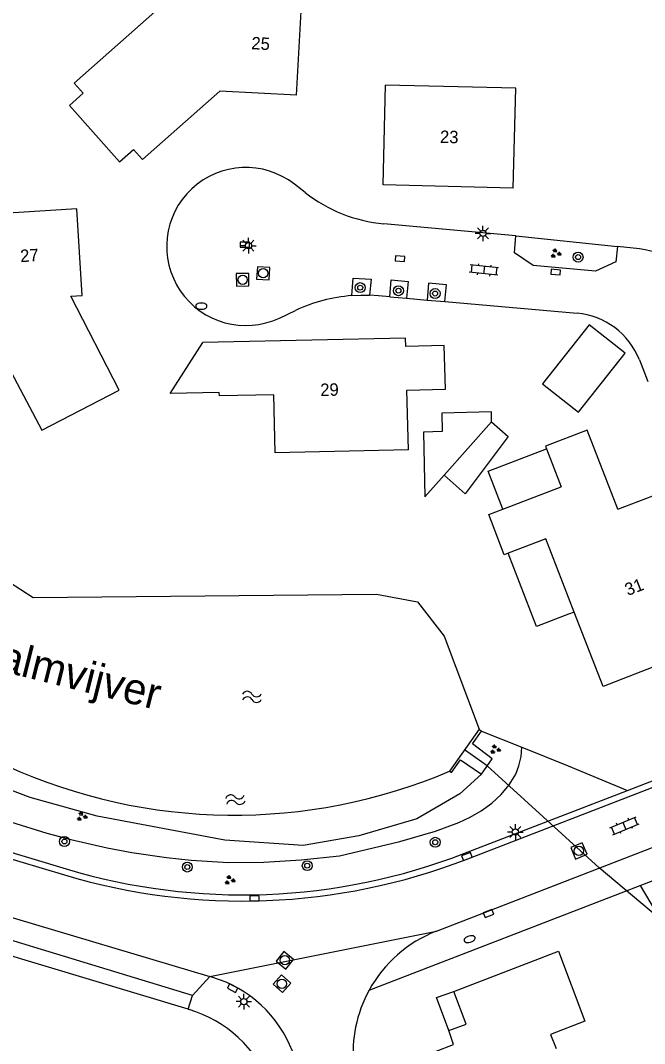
# Model space of a CAD drawing. Extents: x 131000 to 133013, y 393000 to 396501.
# Drawn here: x 131308.3 to 131358.5, y 394977.7 to 395059.9 of the extents above; entities that cross this region are included whole.
import ezdxf

# ---------------------------------------------------------------- set-up
doc = ezdxf.new("R2010")
doc.units = 0
for name, color, linetype in [('gg-afsc-erfafscheiding', 7, 'Continuous'), ('gg-anno-huisnummerreeks BGT', 7, 'Continuous'), ('gg-anno-naam water', 7, 'Continuous'), ('gg-bbg-gedigitaliseerde bebouwing', 7, 'Continuous'), ('gg-bbg-gedigitaliseerde bijgebouw', 7, 'Continuous'), ('gg-bbg-hoofdgebouw', 7, 'Continuous'), ('gg-bbg-luifel en loopbrug', 7, 'Continuous'), ('gg-knt-BGT kruinlijn', 7, 'Continuous'), ('gg-knt-verharding', 7, 'Continuous'), ('gg-knt-verharding nz', 7, 'Continuous'), ('gg-kntw-beschoeiing', 7, 'Continuous'), ('gg-kwrk-duiker nz buis', 7, 'Continuous'), ('gg-kwrk-uitstroombak niveau min 01', 7, 'Continuous'), ('gt-grn-groengrens', 7, 'Continuous'), ('gt-grn-vlakafsluiter', 7, 'Continuous'), ('gt-grn-weggrens', 7, 'Continuous'), ('gt-symb-boom', 7, 'Continuous'), ('gt-symb-brandkraan', 7, 'Continuous'), ('gt-symb-groenvak', 7, 'Continuous'), ('gt-symb-klinker verharding', 7, 'Continuous'), ('gt-symb-kolk', 7, 'Continuous'), ('gt-symb-lichtmast', 7, 'Continuous'), ('gt-symb-rioolschacht', 7, 'Continuous'), ('gt-symb-watersymbool', 7, 'Continuous')]:
    doc.layers.add(name, color=color, linetype=linetype)

# ---------------------------------------------------------------- blocks, each defined once
blk = doc.blocks.new('gt0-LMAST')
at = {"layer": 'gt-symb-lichtmast'}
for p, q in [((-0.182, 0.173), (-0.447, 0.438)), ((-0.005, 0.246), (-0.005, 0.621)), ((0.172, 0.173), (0.437, 0.438)), ((-0.255, -0.004), (-0.63, -0.004)), ((-0.182, -0.181), (-0.447, -0.446)), ((-0.005, -0.254), (-0.005, -0.629)), ((0.437, -0.446), (0.172, -0.181)), ((0.245, -0.004), (0.62, -0.004))]:
    blk.add_line(p, q, dxfattribs=at)
blk.add_circle((-0.005, -0.004), 0.25, dxfattribs=at)
blk = doc.blocks.new('gt0-BR')
at = {"layer": 'gt-symb-brandkraan'}
for centre, radius, start, end in [((-0.244, 0), 0.206, 107.56694, 252.43307), ((0.599, -2.664), 3, 106.89205, 107.56694), ((0, -0.691), 0.938, 73.10799, 106.89205), ((-0.599, -2.664), 3, 72.43309, 73.10799), ((0.244, 0), 0.206, 287.56695, 72.43309), ((0.599, 2.664), 3, 252.43307, 253.10797), ((0, 0.691), 0.938, 253.10797, 286.89206), ((-0.599, 2.664), 3, 286.89206, 287.56695)]:
    blk.add_arc(centre, radius, start, end, dxfattribs=at)
blk = doc.blocks.new('gt0-RS')
at = {"layer": 'gt-symb-rioolschacht'}
blk.add_lwpolyline([(-0.5, -0.5), (0.5, -0.5), (0.5, 0.5), (-0.5, 0.5)], close=True, dxfattribs=at)
blk.add_circle((0, 0), 0.375, dxfattribs=at)
blk = doc.blocks.new('gt0-KOLK')
at = {"layer": 'gt-symb-kolk'}
blk.add_lwpolyline([(0, 0), (0.375, 0), (0.375, 0.4), (-0.375, 0.4), (-0.375, 0), (0, 0)], dxfattribs=at)
blk = doc.blocks.new('gt0-KL1')
at = {"layer": 'gt-symb-klinker verharding'}
for p, q in [((-1.15, 0.3), (1.15, 0.3)), ((-1, -0.3), (-1, 0.3)), ((-0.5, 0.3), (-0.5, 0.45)), ((0, -0.3), (0, 0.3)), ((0.5, 0.3), (0.5, 0.45)), ((1, -0.3), (1, 0.3)), ((-1.15, -0.3), (1.15, -0.3)), ((-0.5, -0.45), (-0.5, -0.3)), ((0.5, -0.45), (0.5, -0.3))]:
    blk.add_line(p, q, dxfattribs=at)
blk = doc.blocks.new('gt0-BOOM')
at = {"layer": 'gt-symb-boom'}
for radius in [0.4, 0.2]:
    blk.add_circle((0, 0), radius, dxfattribs=at)
blk = doc.blocks.new('gt0-GRVAK')
at = {"layer": 'gt-symb-groenvak'}
for p, q in [((-0.11, 0.189), (-0.228, 0.24)), ((-0.182, 0.153), (0.088, 0.153)), ((-0.091, 0.211), (-0.156, 0.322)), ((-0.047, 0.214), (-0.047, 0.393)), ((-0.004, 0.211), (0.061, 0.322)), ((0.015, 0.189), (0.133, 0.24)), ((0.262, -0.052), (0.197, 0.059)), ((0.305, -0.049), (0.305, 0.13)), ((0.349, -0.052), (0.414, 0.059)), ((-0.245, -0.228), (-0.363, -0.177)), ((-0.318, -0.264), (-0.047, -0.264)), ((-0.226, -0.206), (-0.291, -0.095)), ((-0.183, -0.203), (-0.183, -0.024)), ((-0.139, -0.206), (-0.074, -0.095)), ((-0.12, -0.228), (-0.002, -0.177)), ((0.243, -0.074), (0.125, -0.023)), ((0.17, -0.11), (0.441, -0.11)), ((0.368, -0.074), (0.486, -0.023))]:
    blk.add_line(p, q, dxfattribs=at)
blk = doc.blocks.new('gt0-WA')
at = {"layer": 'gt-symb-watersymbool'}
for centre, start, end in [((-0.323, 0.022), 28.07249, 151.92751), ((0.427, 0.422), 208.07248, 331.92751), ((-0.323, -0.428), 28.07249, 151.92751), ((0.427, -0.028), 208.07248, 331.92751)]:
    blk.add_arc(centre, 0.425, start, end, dxfattribs=at)

msp = doc.modelspace()

# ---------------------------------------------------------------- linework, layer by layer
at = {"layer": 'gg-afsc-erfafscheiding'}
msp.add_line((131358.103, 394990.382), (131360.379, 394986.536), dxfattribs=at)
at = {"layer": 'gg-bbg-gedigitaliseerde bebouwing'}
for p, q in [((131324.19, 395034.066), (131322.954, 395034.039)), ((131355.123, 395006.38), (131352.801, 395012.379))]:
    msp.add_line(p, q, dxfattribs=at)
for points in [[(131330.48, 395053.926), (131330.94, 395062.15), (131321.42, 395062.73), (131312.605, 395054.893)], [(131312.605, 395054.893), (131313.326, 395054.086), (131312.22, 395053.099), (131316.259, 395048.575), (131317.365, 395049.562)], [(131347.906, 395046.447), (131348.12, 395054.49), (131337.638, 395054.741)], [(131312.82, 395044.801), (131303.03, 395044.19), (131303.48, 395037.21), (131304.54, 395037.29), (131310, 395027), (131316.237, 395030.206)], [(131324.277, 395030.022), (131320.322, 395029.936), (131322.954, 395034.039)], [(131339.472, 395025.408), (131328.759, 395025.178), (131328.659, 395029.842), (131324.283, 395029.749), (131324.277, 395030.022)], [(131347.495, 395017.107), (131347.18, 395016.986), (131345.943, 395020.208)], [(131352.801, 395012.379), (131350.52, 395018.27), (131347.495, 395017.107)], [(131351.529, 394985.097), (131353.67, 394979.492), (131350.907, 394978.402), (131351.347, 394977.285)]]:
    msp.add_lwpolyline(points, dxfattribs=at)
at = {"layer": 'gg-bbg-gedigitaliseerde bijgebouw'}
for p, q in [((131346.169, 395027.665), (131346.152, 395028.465)), ((131342.346, 395023.383), (131346.169, 395027.665))]:
    msp.add_line(p, q, dxfattribs=at)
msp.add_lwpolyline([(131346.152, 395028.465), (131342.153, 395028.379), (131342.185, 395026.879), (131340.686, 395026.847), (131340.797, 395021.648), (131342.346, 395023.383)], dxfattribs=at)
at = {"layer": 'gg-bbg-hoofdgebouw'}
for p, q in [((131350.581, 395025.503), (131351.761, 395022.444)), ((131347.065, 395020.639), (131351.761, 395022.444)), ((131345.943, 395020.208), (131347.065, 395020.639)), ((131343.12, 394981.878), (131351.529, 394985.097))]:
    msp.add_line(p, q, dxfattribs=at)
for points in [[(131347.906, 395046.447), (131337.439, 395046.713), (131337.638, 395054.741)], [(131330.48, 395053.926), (131324.309, 395054.266), (131318.091, 395048.748), (131317.365, 395049.562)], [(131316.237, 395030.206), (131312.345, 395037.778), (131313.245, 395037.828), (131312.82, 395044.801)], [(131339.472, 395025.408), (131339.358, 395030.219), (131342.445, 395030.286), (131342.358, 395033.809), (131339.263, 395033.733), (131339.249, 395034.389), (131324.19, 395034.066)], [(131356.303, 395020.645), (131353.848, 395027.009), (131350.499, 395025.717), (131350.581, 395025.503)], [(131356.303, 395020.645), (131359.113, 395021.728), (131363.745, 395009.735), (131355.123, 395006.38)], [(131342.72, 394978.732), (131344.127, 394979.25), (131343.12, 394981.878)], [(131342.617, 394969.749), (131340.041, 394976.421), (131343.11, 394977.594), (131342.72, 394978.732)]]:
    msp.add_lwpolyline(points, dxfattribs=at)
at = {"layer": 'gg-bbg-luifel en loopbrug'}
for points in [[(131350.247, 395030.736), (131353.141, 395028.443), (131356.897, 395033.183), (131354.003, 395035.476), (131350.247, 395030.736)], [(131346.169, 395027.665), (131347.484, 395026.491), (131344.04, 395021.87), (131342.346, 395023.383)], [(131347.065, 395020.639), (131345.889, 395023.7), (131350.581, 395025.503)], [(131352.801, 395012.379), (131352.336, 395012.199), (131349.778, 395011.209), (131347.495, 395017.107)], [(131342.72, 394978.732), (131341.748, 394981.373), (131343.12, 394981.878)]]:
    msp.add_lwpolyline(points, dxfattribs=at)
at = {"layer": 'gg-knt-BGT kruinlijn'}
msp.add_lwpolyline([(131307.503, 394995.513), (131310.414, 394994.609), (131312.345, 394994.086), (131315.271, 394993.413), (131317.239, 394993.042), (131320.031, 394992.63), (131322.024, 394992.421), (131325.023, 394992.248), (131327.861, 394992.259), (131330.854, 394992.456), (131333.939, 394992.769), (131338.798, 394993.922), (131341.658, 394994.751), (131343.543, 394995.459), (131344.448, 394995.893), (131345.314, 394996.397), (131346.174, 394997.015), (131346.931, 394997.7), (131347.589, 394998.474), (131348.108, 394999.335), (131348.352, 395000), (131348.543, 395000.768), (131348.594, 395001.499)], dxfattribs=at)
at = {"layer": 'gg-knt-verharding'}
for p, q in [((131331.178, 395046.101), (131330.309, 395046.778)), ((131348.122, 395042.623), (131337.5, 395043.598)), ((131358.048, 395041.566), (131356.278, 395041.755)), ((131337.977, 395037.729), (131339.331, 395037.609)), ((131339.331, 395037.609), (131340.983, 395037.464)), ((131340.983, 395037.464), (131342.408, 395037.338)), ((131329.102, 395036.012), (131330.408, 395036.624)), ((131342.408, 395037.338), (131353.031, 395036.4)), ((131358.047, 395032.659), (131358.735, 395030.922)), ((131341.741, 394986.723), (131394.294, 395007.136)), ((131321.784, 394980.439), (131247.188, 395002.933)), ((131344.118, 394992.489), (131367.358, 395001.475)), ((131357.088, 394998.04), (131362.158, 395000)), ((131290.008, 394998.327), (131311.973, 394991.725)), ((131343.938, 394992.956), (131357.088, 394998.04)), ((131290.124, 394997.77), (131311.829, 394991.246)), ((131358.103, 394990.382), (131375.199, 394996.998)), ((131336.315, 394981.973), (131358.103, 394990.382)), ((131323.51, 394983.065), (131322.115, 394981.536)), ((131323.744, 394982.995), (131323.51, 394983.065)), ((131321.784, 394980.439), (131321.841, 394980.422))]:
    msp.add_line(p, q, dxfattribs=at)
for points in [[(131356.278, 395041.755), (131356.138, 395040.542), (131354.52, 395039.782), (131349.513, 395040.233), (131348.004, 395041.261), (131348.122, 395042.623)], [(131334.917, 395037.818), (131335.042, 395039.23), (131336.474, 395039.137), (131336.36, 395037.851)], [(131337.977, 395037.729), (131338.096, 395039.074), (131339.45, 395038.955), (131339.331, 395037.609)], [(131342.408, 395037.338), (131342.527, 395038.681), (131341.102, 395038.817), (131340.983, 395037.464)], [(131334.917, 395037.818), (131335.64, 395037.855), (131336.36, 395037.851)], [(131337.977, 395037.729), (131337.081, 395037.808), (131336.36, 395037.851)], [(131322.115, 394981.536), (131296.231, 394989.423), (131295.776, 394991.367)]]:
    msp.add_lwpolyline(points, dxfattribs=at)
for centre, radius, start, end in [((131326.401, 395041.765), 6.356, 52.05994, 295.14637), ((131338.601, 395055.614), 12.066, 232.03555, 264.76535), ((131357.334, 395034.859), 6.745, 21.10055, 83.92424), ((131335.94, 395024.842), 13.016, 94.50994, 115.1535), ((131352.508, 395030.466), 5.957, 21.60031, 84.96755), ((131326.161, 395038.942), 49.803, 253.27478, 291.13437), ((131326.161, 395038.942), 49.303, 253.27557, 291.13527), ((131345.539, 394976.91), 10.522, 111.16005, 151.23871), ((131320.905, 394973.499), 9.911, 21.09323, 73.35371), ((131345.529, 394976.922), 10.507, 151.2704, 168.53997), ((131318.895, 394970.658), 10.199, 21.5006, 73.21023), ((131345.522, 394976.921), 10.501, 168.52725, 201.21739)]:
    msp.add_arc(centre, radius, start, end, dxfattribs=at)
at = {"layer": 'gg-knt-verharding nz'}
msp.add_line((131295.776, 394991.367), (131323.51, 394983.065), dxfattribs=at)
at = {"layer": 'gg-kntw-beschoeiing'}
msp.add_lwpolyline([(131267.716, 395027.83), (131270.883, 395029.879), (131282.776, 395029.286), (131290.514, 395027.692), (131293.825, 395025.935), (131296.671, 395023.861), (131306.31, 395015.464), (131309.325, 395013.532), (131336.918, 395013.816), (131340.201, 395013.209), (131342.341, 395010.449), (131345.16, 395002.947)], dxfattribs=at)
msp.add_arc((131325.47, 395040.197), 44.152, 245.56664, 293.0804, dxfattribs=at)
at = {"layer": 'gg-kwrk-duiker nz buis'}
msp.add_lwpolyline([(131364.066, 394984.095), (131362.34, 394985.492), (131354.82, 394991.803), (131345.816, 395000), (131343.984, 395001.285)], dxfattribs=at)
at = {"layer": 'gg-kwrk-uitstroombak niveau min 01'}
for q in [(131342.778, 394999.58), (131345.348, 395002.806)]:
    msp.add_line((131345.16, 395002.947), q, dxfattribs=at)
for points in [[(131345.35, 394999.331), (131346.222, 395000.582), (131344.642, 395001.787), (131345.348, 395002.806)], [(131342.778, 394999.58), (131342.939, 394999.478), (131343.667, 395000.493), (131345.35, 394999.331)]]:
    msp.add_lwpolyline(points, dxfattribs=at)
at = {"layer": 'gt-grn-groengrens'}
msp.add_lwpolyline([(131345.35, 394999.331), (131343.615, 394997.772), (131340.15, 394995.754), (131335.479, 394994.379), (131331.009, 394993.595), (131324.72, 394994.043), (131314.457, 394995.954), (131309.065, 394997.476), (131299.285, 395001.161), (131294.257, 395003.43), (131283.816, 395006.968), (131278.066, 395008.673), (131273.321, 395009.892), (131265.346, 395011.393), (131264.569, 395011.72), (131261.878, 395013.604), (131261.031, 395015.093), (131260.97, 395018.683), (131261.143, 395020.088)], dxfattribs=at)
at = {"layer": 'gt-grn-vlakafsluiter'}
for p, q in [((131348.122, 395042.623), (131356.278, 395041.755)), ((131345.348, 395002.806), (131348.594, 395001.499)), ((131348.594, 395001.499), (131352.317, 395000)), ((131352.317, 395000), (131357.088, 394998.04))]:
    msp.add_line(p, q, dxfattribs=at)
at = {"layer": 'gt-grn-weggrens'}
for p, q in [((131323.51, 394983.065), (131341.741, 394986.723)), ((131321.784, 394980.439), (131322.115, 394981.536))]:
    msp.add_line(p, q, dxfattribs=at)

# ---------------------------------------------------------------- block references
at = {"layer": 'gt-symb-boom', "rotation": 90}
msp.add_blockref('gt0-BOOM', (131353.116, 395040.913), dxfattribs=at)
at = {"layer": 'gt-symb-boom'}
for p in [(131335.602, 395038.459), (131338.678, 395038.213), (131341.625, 395037.983), (131311.829, 394993.927), (131341.631, 394993.866), (131321.705, 394991.874), (131331.346, 394991.984)]:
    msp.add_blockref('gt0-BOOM', p, dxfattribs=at)
at = {"layer": 'gt-symb-brandkraan'}
msp.add_blockref('gt0-BR', (131322.832, 395036.971), dxfattribs=at)
at = {"layer": 'gt-symb-brandkraan', "rotation": 15.189787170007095}
msp.add_blockref('gt0-BR', (131344.4, 394986.074), dxfattribs=at)
at = {"layer": 'gt-symb-groenvak'}
for p in [(131351.309, 395041.203), (131346.45, 395001.326), (131313.21, 394995.929), (131325.103, 394990.817)]:
    msp.add_blockref('gt0-GRVAK', p, dxfattribs=at)
at = {"layer": 'gt-symb-klinker verharding'}
for p, rotation in [((131345.549, 395039.877), 173.79902900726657), ((131356.848, 394995.187), 22.76972663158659)]:
    msp.add_blockref('gt0-KL1', p, dxfattribs=dict(at, rotation=rotation))
at = {"layer": 'gt-symb-kolk'}
msp.add_blockref('gt0-KOLK', (131326.318, 395041.709), dxfattribs=at)
for p, rotation in [((131338.786, 395040.585), -5.163306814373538), ((131351.294, 395039.511), -5.1633068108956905), ((131344.25, 394992.54), 21.099212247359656), ((131327.108, 394989.153), 0.8020885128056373), ((131345.843, 394988.318), -158.77323173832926), ((131325.44, 394982.304), 152.48693881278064)]:
    msp.add_blockref('gt0-KOLK', p, dxfattribs=dict(at, rotation=rotation))
at = {"layer": 'gt-symb-lichtmast'}
for p in [(131345.476, 395042.819), (131326.627, 395041.834), (131348.079, 394994.689), (131326.253, 394981.059)]:
    msp.add_blockref('gt0-LMAST', p, dxfattribs=at)
at = {"layer": 'gt-symb-rioolschacht'}
for p, rotation in [((131327.802, 395039.616), -3.383287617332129), ((131326.152, 395039.094), 1.088488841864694), ((131353.185, 394993.171), 22.514112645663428), ((131329.543, 394984.379), 50.803311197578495), ((131329.31, 394982.49), 48.161850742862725)]:
    msp.add_blockref('gt0-RS', p, dxfattribs=dict(at, rotation=rotation))
at = {"layer": 'gt-symb-watersymbool'}
for p, rotation in [((131326.848, 395005.56), 0.5729386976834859), ((131325.514, 394997.285), 10.366322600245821)]:
    msp.add_blockref('gt0-WA', p, dxfattribs=dict(at, rotation=rotation))

# ---------------------------------------------------------------- texts
at = {"layer": 'gg-anno-huisnummerreeks BGT'}
for s, rotation, p in [('25', 356.8, (131326.83, 395057.633)), ('23', 358.6, (131342.004, 395050.097)), ('27', 3.5, (131308.297, 395040.503)), ('29', 1.2, (131332.399, 395029.742)), ('31', 21.1, (131357.107, 395013.661))]:
    msp.add_text(s, height=1, rotation=rotation, dxfattribs=at).set_placement(p)
at = {"layer": 'gg-anno-naam water'}
msp.add_text('Swalmvijver', height=2.5, rotation=345.99156, dxfattribs=at).set_placement((131301.923, 395008.817))

doc.saveas('drawing.dxf')
